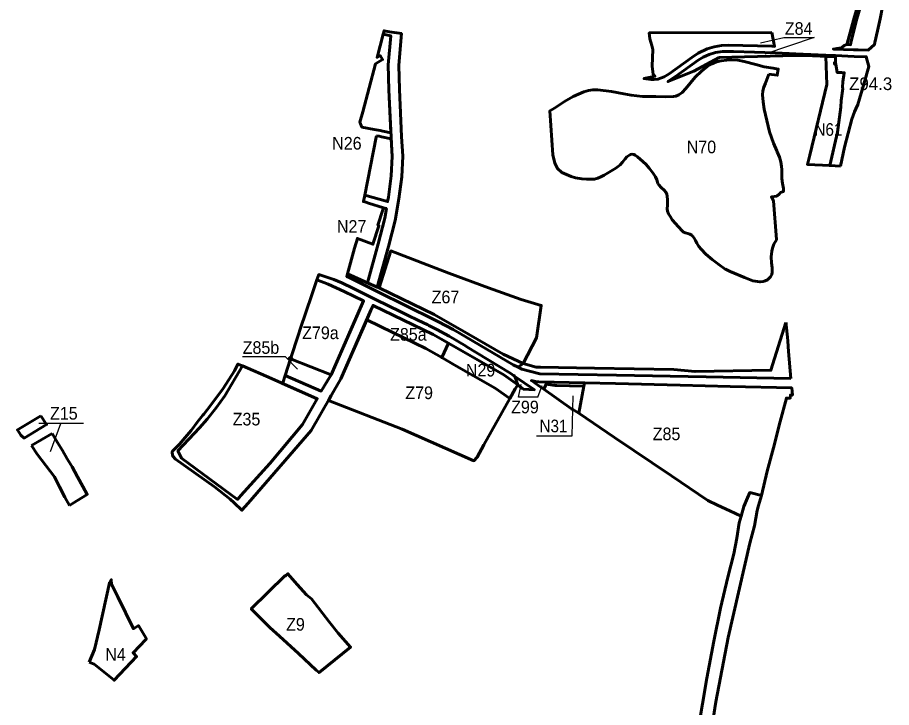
# Model space of a CAD drawing. Extents: x -650277 to -643420, y -1073980 to -1066720.
# Drawn here: x -646636 to -644975, y -1072009 to -1070698 of the extents above; entities that cross this region are included whole.
import ezdxf

# ---------------------------------------------------------------- set-up
doc = ezdxf.new("R2010")
doc.units = 0
doc.header["$LTSCALE"] = 9.6
doc.header["$PDMODE"] = 32
doc.header["$PDSIZE"] = 4.8
for name, color, linetype, lineweight in [('1', 7, 'Continuous', 60), ('11', 7, 'Continuous', 60), ('15', 7, 'Continuous', 60), ('18', 7, 'Continuous', 60), ('20', 7, 'Continuous', 60), ('24', 7, 'Continuous', 60), ('40', 7, 'Continuous', 60), ('45', 7, 'Continuous', 60), ('60', 7, 'Continuous', 60), ('63', 7, 'Continuous', 25), ('7', 7, 'Continuous', 60)]:
    doc.layers.add(name, color=color, linetype=linetype, lineweight=lineweight)

msp = doc.modelspace()

# ---------------------------------------------------------------- linework, layer by layer
at = {"layer": '1'}
msp.add_line((-646609.21, -1071510.98), (-646570, -1071488.38), dxfattribs=at)
for points in [[(-646591.65, -1071454.91), (-646635.79, -1071481.6), (-646629.37, -1071491.74), (-646623.18, -1071496.99), (-646580.58, -1071471.48)], [(-646102.04, -1071906.4), (-646068.317, -1071937.555), (-646062.91, -1071942.55), (-646002.93, -1071893.984), (-646026.64, -1071867.44), (-646043.49, -1071845.87), (-646077.32, -1071802.59), (-646087, -1071795), (-646104.5, -1071774.86), (-646122.16, -1071754.78), (-646127.12, -1071759.15), (-646127.84, -1071758.53), (-646191.57, -1071821.44), (-646174.69, -1071838.69), (-646156.59, -1071856.53), (-646137.74, -1071873.31)]]:
    msp.add_lwpolyline(points, close=True, dxfattribs=at)
for points in [[(-646570, -1071488.38), (-646559.53, -1071505.12), (-646550.23, -1071520.88), (-646541.14, -1071536.3), (-646532.04, -1071551.72), (-646521.8, -1071570.34), (-646511.47, -1071589.11), (-646503.31, -1071603.95), (-646531.2, -1071621.07), (-646537.28, -1071624.8)], [(-646537.28, -1071624.8), (-646545.89, -1071609.07), (-646555.78, -1071589.66), (-646565.17, -1071570.4), (-646598.63, -1071527.8), (-646609.21, -1071510.98)]]:
    msp.add_lwpolyline(points, dxfattribs=at)
at = {"layer": '11'}
msp.add_lwpolyline([(-646066.165, -1071422.155), (-646153.5, -1071383.85), (-646208.577, -1071360.044), (-646241.68, -1071416.887), (-646258.487, -1071439.265), (-646275.615, -1071460.886), (-646289.976, -1071477.514), (-646330.914, -1071521.11), (-646324, -1071535), (-646217.978, -1071613.552), (-646211.407, -1071606.247), (-646156.471, -1071545.166), (-646094.063, -1071471.007)], close=True, dxfattribs=at)
at = {"layer": '15'}
for points in [[(-645039.574, -1070675.065), (-645045.493, -1070696.321), (-645059.308, -1070747.712), (-645059.403, -1070749.195), (-645053.21, -1070749.75), (-645052.4, -1070746.427), (-645046.63, -1070722.77), (-645041, -1070700.44), (-645033.53, -1070674.55)], [(-645955.342, -1071233.725), (-645973.324, -1071224.925), (-645989.7, -1071216.91), (-645997.62, -1071213.03), (-646019.41, -1071202.36), (-646035.06, -1071195.87), (-646063.59, -1071186.33), (-646067.097, -1071196.699), (-646045.462, -1071204.917), (-646015.387, -1071218.854), (-645978.403, -1071236.481), (-646040.084, -1071376.813), (-646058.719, -1071407.796), (-646127.301, -1071378.036), (-646131.79, -1071391.83), (-646132.229, -1071393.179), (-646066.165, -1071422.155), (-646094.063, -1071471.007), (-646156.471, -1071545.166), (-646211.407, -1071606.247), (-646217.978, -1071613.552)], [(-645701.44, -1071372.25), (-645782.32, -1071323.5), (-645784.92, -1071321.93), (-645815.65, -1071303.41), (-645839.37, -1071290.6), (-645854.1, -1071282.93), (-645856.26, -1071281.91), (-645875.48, -1071272.81), (-645893.41, -1071264.04), (-645907.62, -1071257.08), (-645955.342, -1071233.725)], [(-646223.928, -1071620.168), (-646209.322, -1071634.004), (-646197.398, -1071620.579), (-646077.593, -1071482.499), (-646021.674, -1071384.575), (-645964.396, -1071254.314), (-645960.34, -1071245.09)], [(-645960.34, -1071245.09), (-645846, -1071300), (-645712, -1071377)], [(-646217.978, -1071613.552), (-646324, -1071535), (-646330.914, -1071521.11), (-646289.976, -1071477.514), (-646275.615, -1071460.886), (-646275.615, -1071460.886), (-646258.487, -1071439.265), (-646241.68, -1071416.887), (-646208.577, -1071360.044), (-646217.049, -1071356.382), (-646220.61, -1071363.16), (-646223.77, -1071369.24), (-646245.1, -1071403.04), (-646269.2, -1071435.22), (-646281.99, -1071451.4), (-646283.52, -1071453.34), (-646293.87, -1071466.43), (-646306.14, -1071482.86), (-646317.52, -1071496.12), (-646327.97, -1071508.29), (-646341.88, -1071522.81), (-646341.66, -1071524.87), (-646340.93, -1071531.64), (-646335.3, -1071537.05), (-646261.46, -1071589.38), (-646231.43, -1071613.06), (-646223.928, -1071620.168)], [(-645712, -1071377), (-645685.098, -1071395.824), (-645690.677, -1071379.721)]]:
    msp.add_lwpolyline(points, dxfattribs=at)
for points in [[(-645911.345, -1070788.463), (-645906.373, -1070728.716), (-645929.077, -1070725.068), (-645939.27, -1070723.43), (-645940.955, -1070729.799), (-645926.784, -1070732.812), (-645931.369, -1070787.913), (-645930.036, -1070835.367), (-645926.084, -1070925.481), (-645923.919, -1070961.855), (-645925.626, -1070998.754), (-645931.24, -1071039.686), (-645932.635, -1071047.688), (-645976.17, -1071035.39), (-645978.58, -1071047.68), (-645973.77, -1071049.17), (-645968.97, -1071050.66), (-645940.25, -1071059.59), (-645934.978, -1071061.119), (-645938.15, -1071079.311), (-645950.283, -1071128.057), (-645970.966, -1071202.169), (-645952.419, -1071210.117), (-645930.943, -1071133.161), (-645918.57, -1071083.449), (-645911.474, -1071042.764), (-645905.69, -1071000.578), (-645903.891, -1070961.723), (-645906.11, -1070924.449), (-645910.048, -1070834.649)], [(-645694.15, -1071357.83), (-645684.785, -1071362.539), (-645674.947, -1071355.071), (-645713.428, -1071337.765), (-645778.69, -1071299.362), (-645844.079, -1071262.487), (-645948.761, -1071211.885), (-645967, -1071204), (-646008.714, -1071184.746), (-646010.14, -1071190.08), (-646004.65, -1071192.55), (-645951.118, -1071219.11), (-645843.45, -1071272.53), (-645835.76, -1071276.35), (-645808.13, -1071290.78), (-645795.97, -1071297.93), (-645694.15, -1071357.83)]]:
    msp.add_lwpolyline(points, close=True, dxfattribs=at)
msp.add_arc((-645538.107, -1071148.434), 277.076, 233.87926, 236.5888, dxfattribs=at)
at = {"layer": '18'}
for points in [[(-645678.86, -1071233.58), (-645741.09, -1071211.36), (-645816.47, -1071183.63), (-645926.81, -1071141.595), (-645948.761, -1071211.885)], [(-645948.761, -1071211.885), (-645844.079, -1071262.487), (-645778.69, -1071299.362), (-645713.428, -1071337.765), (-645674.947, -1071355.071)], [(-645674.947, -1071355.071), (-645650.09, -1071306.433), (-645640.737, -1071244.963), (-645678.86, -1071233.58)]]:
    msp.add_lwpolyline(points, dxfattribs=at)
at = {"layer": '20'}
for points in [[(-645990.48, -1071263.958), (-645978.403, -1071236.481), (-646015.387, -1071218.854), (-646045.462, -1071204.917), (-646067.097, -1071196.699), (-646076.713, -1071225.138)], [(-646076.713, -1071225.138), (-646098.66, -1071290.03), (-646102.011, -1071300.326), (-646117.031, -1071346.48)], [(-646117.031, -1071346.48), (-646040.084, -1071376.813), (-645990.48, -1071263.958)]]:
    msp.add_lwpolyline(points, dxfattribs=at)
msp.add_lwpolyline([(-645972.423, -1071272.568), (-646021.674, -1071384.575), (-646039.658, -1071416.067), (-646044.948, -1071425.333), (-645905.027, -1071480.359), (-645768.62, -1071540.17), (-645762.54, -1071533.015), (-645749.631, -1071509.908), (-645700.38, -1071421.746), (-645728.054, -1071402.382), (-645806.036, -1071357.564), (-645829.706, -1071343.963), (-645859.986, -1071326.563), (-645923.023, -1071296.291), (-645972.422, -1071272.568)], close=True, dxfattribs=at)
msp.add_point((-646117.031, -1071346.48), dxfattribs=at)
at = {"layer": '24'}
msp.add_lwpolyline([(-645303, -1070774), (-645182, -1070771), (-645161, -1070770), (-645143, -1070770), (-645125.217, -1070770.81), (-645081.75, -1070772.79), (-645081.6, -1070770.362), (-645100.32, -1070769.5), (-645156.988, -1070766.884), (-645195.527, -1070765.319), (-645195.527, -1070765.319), (-645275.8, -1070762.66), (-645296.51, -1070762.52), (-645309.78, -1070764.88), (-645321.9, -1070768.47), (-645333.12, -1070773.33), (-645342.94, -1070779.31), (-645385.99, -1070810.35), (-645400.05, -1070819.84), (-645351, -1070800)], close=True, dxfattribs=at)
at = {"layer": '40'}
for points in [[(-645926.457, -1070916.969), (-645930.036, -1070835.367), (-645931.369, -1070787.913), (-645926.784, -1070732.812), (-645940.955, -1070729.799), (-645952.65, -1070773.98), (-645946.81, -1070770.47), (-645942.3, -1070777.96), (-645955.86, -1070786.21), (-645980.01, -1070877.28), (-645985.28, -1070897.13), (-645981.48, -1070906.35), (-645958.21, -1070910.84)], [(-645958.21, -1070910.84), (-645946.85, -1070913.03), (-645941.94, -1070913.98), (-645926.457, -1070916.969)], [(-645954.01, -1070922.8), (-645954.492, -1070925.251), (-645976.17, -1071035.39), (-645932.635, -1071047.688), (-645931.24, -1071039.686), (-645925.626, -1070998.754), (-645923.919, -1070961.855), (-645925.908, -1070928.435)], [(-645925.908, -1070928.435), (-645944.08, -1070924.79), (-645948.99, -1070923.81), (-645954.01, -1070922.8)]]:
    msp.add_lwpolyline(points, dxfattribs=at)
for points in [[(-645970.966, -1071202.169), (-645950.283, -1071128.057), (-645938.15, -1071079.311), (-645934.978, -1071061.119), (-645940.25, -1071059.59), (-645941.45, -1071063.3), (-645950.96, -1071092.8), (-645949.21, -1071093.62), (-645960.66, -1071128.71), (-645990.14, -1071117.76), (-645995.74, -1071136.22), (-646008.714, -1071184.746)], [(-645700.38, -1071421.746), (-645690.056, -1071403.266), (-645685.098, -1071395.824), (-645712, -1071377), (-645816.714, -1071316.828), (-645829.706, -1071343.963), (-645806.036, -1071357.564), (-645728.054, -1071402.382)], [(-645583.18, -1071441.3), (-645580.947, -1071442.658), (-645569.07, -1071449.88), (-645560.11, -1071398.7), (-645611.58, -1071397.14), (-645631.44, -1071394.9), (-645635.795, -1071404.403)]]:
    msp.add_lwpolyline(points, close=True, dxfattribs=at)
at = {"layer": '45'}
for points in [[(-645100.268, -1070771.946), (-645098.438, -1070825.558), (-645130.749, -1070959.561), (-645134.972, -1070977.077), (-645092.67, -1070979.52)], [(-645083.49, -1070786.92), (-645083.95, -1070783.89), (-645081.57, -1070783.53), (-645081.85, -1070781.59), (-645081.75, -1070772.79), (-645100.268, -1070771.946)], [(-645255.407, -1070781.443), (-645267.315, -1070779.162), (-645279.349, -1070778.402), (-645288.343, -1070778.909), (-645298.731, -1070780.176), (-645307.923, -1070782.557), (-645317.677, -1070786.866), (-645325.785, -1070791.428), (-645336.046, -1070799.793), (-645348.318, -1070811.675)], [(-645208.696, -1070805.535), (-645192.298, -1070807.665), (-645190.59, -1070796.152), (-645200.111, -1070794.621), (-645217.086, -1070791.58), (-645233.003, -1070787.399), (-645255.407, -1070781.443)], [(-645092.67, -1070979.52), (-645078.23, -1070915.65), (-645071.77, -1070868.73), (-645071.18, -1070855.63), (-645068.07, -1070832.72), (-645068.52, -1070830.52), (-645068.07, -1070820.37), (-645065.01, -1070803.22), (-645070.2, -1070802.33), (-645078.85, -1070802.46), (-645081.13, -1070786.56), (-645083.49, -1070786.92)], [(-645199.714, -1070937.126), (-645206.872, -1070914.991), (-645216.991, -1070872.38), (-645219.351, -1070858.481), (-645220.312, -1070845.02), (-645219.787, -1070837.502), (-645217.778, -1070830.159), (-645215.063, -1070822.589), (-645208.696, -1070805.535)], [(-645348.318, -1070811.675), (-645366.02, -1070832.94), (-645373.241, -1070840.417), (-645379.448, -1070845.106), (-645385.148, -1070847.387), (-645389.329, -1070848.148), (-645404.15, -1070848.781), (-645423.364, -1070848.402)], [(-645507.299, -1070838.899), (-645533.268, -1070835.731), (-645542.642, -1070835.35), (-645550.832, -1070836.602), (-645560.079, -1070839.137)], [(-645560.079, -1070839.137), (-645579.841, -1070848.008), (-645596.689, -1070857.387), (-645615.817, -1070870.187), (-645624.321, -1070875.224), (-645618.798, -1070958.861), (-645615, -1070975), (-645610, -1070985), (-645601.41, -1070992.83)], [(-645470.235, -1070845.487), (-645483.61, -1070843.208), (-645507.299, -1070838.899)], [(-645423.364, -1070848.402), (-645448.7, -1070847.895), (-645470.235, -1070845.487)], [(-645192.548, -1070953.47), (-645193.51, -1070951.2), (-645199.714, -1070937.126)], [(-645183.833, -1070986.74), (-645184.357, -1070981.146), (-645185.843, -1070972.23), (-645188.377, -1070963.313), (-645192.548, -1070953.47)], [(-645494.223, -1070980.781), (-645490.641, -1070977.722), (-645486.534, -1070972.652), (-645481.466, -1070966.271)], [(-645481.466, -1070966.271), (-645477.971, -1070963.036), (-645474.301, -1070960.414), (-645471.418, -1070958.578), (-645468.185, -1070957.966), (-645464.865, -1070958.491), (-645462.069, -1070959.89)], [(-645462.069, -1070959.89), (-645457.875, -1070962.949), (-645452.982, -1070967.057), (-645448.001, -1070971.341), (-645441.361, -1070977.635)], [(-645554.524, -1071005.405), (-645548.534, -1071005.316), (-645539.622, -1071004.966), (-645533.156, -1071003.131), (-645527.302, -1071001.033), (-645521.535, -1070997.886), (-645499.204, -1070984.54), (-645494.223, -1070980.781)], [(-645441.361, -1070977.635), (-645435.443, -1070984.082), (-645428.541, -1070993.348), (-645423.648, -1071000.865)], [(-645180.506, -1071022.778), (-645182.261, -1071013.633), (-645183.746, -1071003.786), (-645183.833, -1070986.74)], [(-645601.41, -1070992.83), (-645583.707, -1071000.16), (-645575.406, -1071002.782), (-645563.698, -1071004.618), (-645554.524, -1071005.405)], [(-645423.648, -1071000.865), (-645421.21, -1071006.61), (-645419.026, -1071013.254)], [(-645419.026, -1071013.254), (-645417.453, -1071016.051), (-645412.735, -1071020.771), (-645407.492, -1071025.841)], [(-645407.492, -1071025.841), (-645404.172, -1071029.687), (-645402.194, -1071033.492), (-645401.408, -1071037.251), (-645400.796, -1071044.157), (-645401.233, -1071054.647)], [(-645202.951, -1071141.698), (-645201.648, -1071136.226), (-645198.678, -1071128.971), (-645198.678, -1071128.971), (-645193.872, -1071120.142), (-645193.872, -1071120.142), (-645193.592, -1071119.776), (-645199.57, -1071046.58), (-645203.66, -1071038.81), (-645193.24, -1071037.31), (-645188.39, -1071032.86), (-645186.18, -1071030.83), (-645180.72, -1071028.86), (-645180.506, -1071022.778)], [(-645401.233, -1071054.647), (-645401.408, -1071061.465), (-645400.796, -1071065.748), (-645398.979, -1071070.938), (-645395.234, -1071076.602), (-645395.222, -1071076.62), (-645391.902, -1071082.302)], [(-645391.902, -1071082.302), (-645380.193, -1071095.851), (-645373.291, -1071103.543), (-645370.698, -1071105.6), (-645367.028, -1071107.348), (-645362.223, -1071108.484), (-645358.326, -1071109.586), (-645358.203, -1071109.621)], [(-645358.203, -1071109.621), (-645354.883, -1071111.631), (-645352, -1071114.429), (-645349.99, -1071117.401)], [(-645349.99, -1071117.401), (-645347.631, -1071121.771), (-645345.097, -1071126.754)], [(-645345.097, -1071126.754), (-645341.689, -1071132.873), (-645336.884, -1071138.467), (-645328.059, -1071147.471), (-645316.308, -1071157.576), (-645303.551, -1071167.541), (-645291.581, -1071175.845), (-645290.83, -1071176.217), (-645281.707, -1071180.74)], [(-645211.07, -1071196.464), (-645207.575, -1071193.492), (-645205.049, -1071190.531), (-645202.777, -1071186.423), (-645201.903, -1071181.615), (-645202.34, -1071173.66), (-645203.301, -1071164.132), (-645203.738, -1071152.537), (-645202.951, -1071141.698)], [(-645281.707, -1071180.74), (-645254.845, -1071191.919), (-645238.506, -1071198.212)], [(-645238.506, -1071198.212), (-645225.487, -1071200.398), (-645225.487, -1071200.398), (-645219.283, -1071199.786), (-645215.351, -1071198.562), (-645211.07, -1071196.464)]]:
    msp.add_lwpolyline(points, dxfattribs=at)
at = {"layer": '60'}
for points in [[(-645033.53, -1070674.55), (-645041, -1070700.44), (-645046.63, -1070722.77), (-645052.4, -1070746.427), (-645053.21, -1070749.75), (-645060.46, -1070749.1), (-645065.17, -1070751.39), (-645070.3, -1070755.92), (-645079.38, -1070756.91), (-645085.58, -1070758.04), (-645047.39, -1070759.71), (-645038.44, -1070759.83), (-645019.57, -1070760.07), (-645007.68, -1070749.5), (-645006.739, -1070745.384), (-645001.71, -1070723.39), (-644997.14, -1070700.88), (-644992.6, -1070677.92)], [(-645071.99, -1070980.72), (-645064.39, -1070944.7), (-645050.47, -1070891.48), (-645045.74, -1070877.19), (-645043, -1070871.35), (-645039.25, -1070863.33), (-645028.25, -1070824.83), (-645018.18, -1070791.34), (-645023.25, -1070772.62), (-645046.46, -1070771.98), (-645081.6, -1070770.362), (-645081.75, -1070772.79), (-645081.85, -1070781.59), (-645081.57, -1070783.53)], [(-645081.57, -1070783.53), (-645083.95, -1070783.89), (-645083.49, -1070786.92), (-645081.13, -1070786.56), (-645078.85, -1070802.46), (-645070.2, -1070802.33)], [(-645070.2, -1070802.33), (-645065.01, -1070803.22), (-645068.07, -1070820.37)], [(-645068.07, -1070820.37), (-645068.52, -1070830.52), (-645068.07, -1070832.72), (-645071.18, -1070855.63), (-645071.77, -1070868.73), (-645078.23, -1070915.65)], [(-645078.23, -1070915.65), (-645092.67, -1070979.52), (-645071.99, -1070980.72)], [(-645176.14, -1071277.26), (-645204.341, -1071368.19), (-645348.55, -1071370.559), (-645388.619, -1071366.991), (-645539.738, -1071364.092), (-645642.431, -1071362.259), (-645650.28, -1071362.07), (-645674.947, -1071355.071), (-645684.785, -1071362.539), (-645677.58, -1071366.16), (-645643.56, -1071374.75), (-645497.84, -1071377.53), (-645327.76, -1071380.76), (-645166.34, -1071384.07)], [(-645166.34, -1071384.07), (-645170.91, -1071332.86), (-645172.03, -1071312.96), (-645172.85, -1071305.45), (-645175.4, -1071281.93), (-645175.67, -1071279.45), (-645176.14, -1071277.26)], [(-645222.48, -1071606.08), (-645244.81, -1071600.61), (-645248.786, -1071610.383), (-645255.662, -1071626.67)], [(-645339.904, -1072462.677), (-645347.551, -1072443.527), (-645347.677, -1072391.355), (-645346.62, -1072330.914), (-645343.458, -1072278.998), (-645339.908, -1072235.158), (-645335.367, -1072185.207), (-645325.498, -1072102.789), (-645309.01, -1071998.147), (-645285.617, -1071875.733), (-645244.798, -1071696.585), (-645235.793, -1071663.703), (-645230.436, -1071634.261), (-645227.905, -1071625.277), (-645222.48, -1071606.08)], [(-645255.662, -1071626.67), (-645261.094, -1071645.025), (-645264.841, -1071657.687), (-645269.077, -1071687.396), (-645274.868, -1071717.176), (-645286.175, -1071761.228), (-645300.076, -1071820.179), (-645313.153, -1071883.081)], [(-645313.153, -1071883.081), (-645326.343, -1071952.807), (-645334.118, -1072001.954), (-645339.455, -1072031.565), (-645344.819, -1072081.225), (-645351.358, -1072130.815), (-645361.317, -1072232.824), (-645364.435, -1072280.268), (-645366.951, -1072331.609), (-645370.624, -1072401.447), (-645372.228, -1072438.764)]]:
    msp.add_lwpolyline(points, dxfattribs=at)
for points in [[(-645202.41, -1070726.571), (-645197.539, -1070753.128), (-645202.96, -1070752.89), (-645285.11, -1070750.69), (-645298.41, -1070751.48), (-645312.2, -1070753.77), (-645325.82, -1070757.94), (-645342.41, -1070765.76), (-645354.98, -1070774.28), (-645398.04, -1070805.44), (-645407.37, -1070810.95), (-645419.18, -1070815.44), (-645426.36, -1070815.78), (-645432.07, -1070816.05), (-645445.81, -1070814.06), (-645429.993, -1070810.647), (-645424.969, -1070809.563), (-645428.39, -1070806.09), (-645430, -1070790.68), (-645428.73, -1070758.67), (-645430.84, -1070751.43), (-645434.53, -1070738.77), (-645435.711, -1070727.497)], [(-645303, -1070774), (-645182, -1070771), (-645161, -1070770), (-645143, -1070770), (-645125.217, -1070770.81), (-645081.75, -1070772.79), (-645081.6, -1070770.362), (-645100.32, -1070769.5), (-645156.988, -1070766.884), (-645195.527, -1070765.319), (-645195.527, -1070765.319), (-645275.8, -1070762.66), (-645296.51, -1070762.52), (-645309.78, -1070764.88), (-645321.9, -1070768.47), (-645333.12, -1070773.33), (-645342.94, -1070779.31), (-645385.99, -1070810.35), (-645400.05, -1070819.84), (-645351, -1070800)], [(-645816.714, -1071316.828), (-645846, -1071300), (-645960.34, -1071245.09), (-645964.396, -1071254.314), (-645972.422, -1071272.568), (-645972.422, -1071272.568), (-645923.023, -1071296.291), (-645859.986, -1071326.563), (-645829.705, -1071343.962)], [(-646045.393, -1071385.64), (-646040.084, -1071376.813), (-646117.031, -1071346.48), (-646127.301, -1071378.036), (-646058.719, -1071407.796)], [(-645675.177, -1071403.922), (-645675.177, -1071403.922), (-645653.742, -1071405.36), (-645690.677, -1071379.721), (-645685.098, -1071395.824)], [(-645614.201, -1071396.844), (-645560.11, -1071398.7), (-645558.872, -1071391.801), (-645558.9, -1071391.8), (-645645.368, -1071389.96), (-645651.93, -1071389.82), (-645659.6, -1071387.71), (-645647.727, -1071396.036), (-645635.795, -1071404.403), (-645631.44, -1071394.9)], [(-645560.11, -1071398.7), (-645569.07, -1071449.88), (-645501.37, -1071495.68), (-645393.34, -1071568.75), (-645324.17, -1071615.53), (-645324.17, -1071615.53), (-645305.78, -1071624.13), (-645282.54, -1071634.997), (-645261.094, -1071645.025), (-645255.662, -1071626.67), (-645248.786, -1071610.383), (-645244.81, -1071600.61), (-645222.48, -1071606.08), (-645222.48, -1071606.08), (-645211.27, -1071560.01), (-645199.61, -1071515.68), (-645186.67, -1071465.55), (-645175.06, -1071420.93), (-645167.58, -1071421.19), (-645167.37, -1071415.2), (-645163.56, -1071415.3), (-645164.76, -1071401.79), (-645281.92, -1071398.82), (-645376.87, -1071396.41), (-645499.65, -1071393.3), (-645558.9, -1071391.8), (-645645.368, -1071389.96), (-645651.93, -1071389.82), (-645659.6, -1071387.71), (-645647.727, -1071396.036), (-645635.795, -1071404.403), (-645631.44, -1071394.9), (-645614.201, -1071396.844)]]:
    msp.add_lwpolyline(points, close=True, dxfattribs=at)
at = {"layer": '63'}
for p, q in [((-645647, -1071419), (-645639, -1071397)), ((-646510.087, -1071469.269), (-646595.257, -1071469.269)), ((-646572.844, -1071522.353), (-646553.419, -1071469.269))]:
    msp.add_line(p, q, dxfattribs=at)
for points in [[(-645224, -1070746), (-645180, -1070736), (-645122, -1070736), (-645216, -1070768)], [(-646208, -1071342), (-646127, -1071342), (-646104, -1071366)], [(-645647, -1071419), (-645684, -1071419), (-645679, -1071395)], [(-645650, -1071493), (-645582, -1071493), (-645580, -1071417)]]:
    msp.add_lwpolyline(points, dxfattribs=at)
at = {"layer": '7'}
for points in [[(-646453.04, -1071956.3), (-646451.87, -1071956.88), (-646409.4, -1071912.17), (-646416.2, -1071904.81), (-646391.83, -1071879.32), (-646390.732, -1071878.171), (-646405.99, -1071853.26), (-646415.46, -1071859.05), (-646445.115, -1071798.418), (-646456.96, -1071774.2), (-646457.52, -1071765.98), (-646461.09, -1071771.76), (-646480.81, -1071861.18), (-646489.34, -1071898.61), (-646499.741, -1071922.455)], [(-646499.741, -1071922.455), (-646490.111, -1071926.754), (-646453.04, -1071956.3)]]:
    msp.add_lwpolyline(points, dxfattribs=at)

# ---------------------------------------------------------------- texts
at = {"layer": '63'}
for s, width, p in [('Z84', 0.95, (-645178, -1070731)), ('N61', 0.9, (-645121.693, -1070922.874)), ('N26', 0.95, (-646038, -1070949)), ('N70', 0.95, (-645364.436, -1070956.045)), ('N27', 0.95, (-646029, -1071107)), ('Z67', 0.95, (-645849, -1071241)), ('Z79a', 0.95, (-646095, -1071309)), ('Z85a', 0.95, (-645928, -1071312)), ('Z85b', 0.95, (-646208, -1071337)), ('N29', 0.95, (-645784, -1071380)), ('Z79', 0.95, (-645899, -1071423)), ('Z99', 0.95, (-645698, -1071450)), ('Z15', 0.95, (-646574, -1071462)), ('Z35', 0.95, (-646227, -1071473)), ('N31', 0.9, (-645644, -1071486)), ('Z85', 0.95, (-645429, -1071501)), ('Z9', 0.95, (-646125.48, -1071862.818)), ('N4', 0.95, (-646469, -1071920))]:
    msp.add_text(s, height=24, dxfattribs=dict(at, width=width)).set_placement(p)
msp.add_text('Z94.3', height=24, dxfattribs=at).set_placement((-645056, -1070836))

doc.saveas('drawing.dxf')
